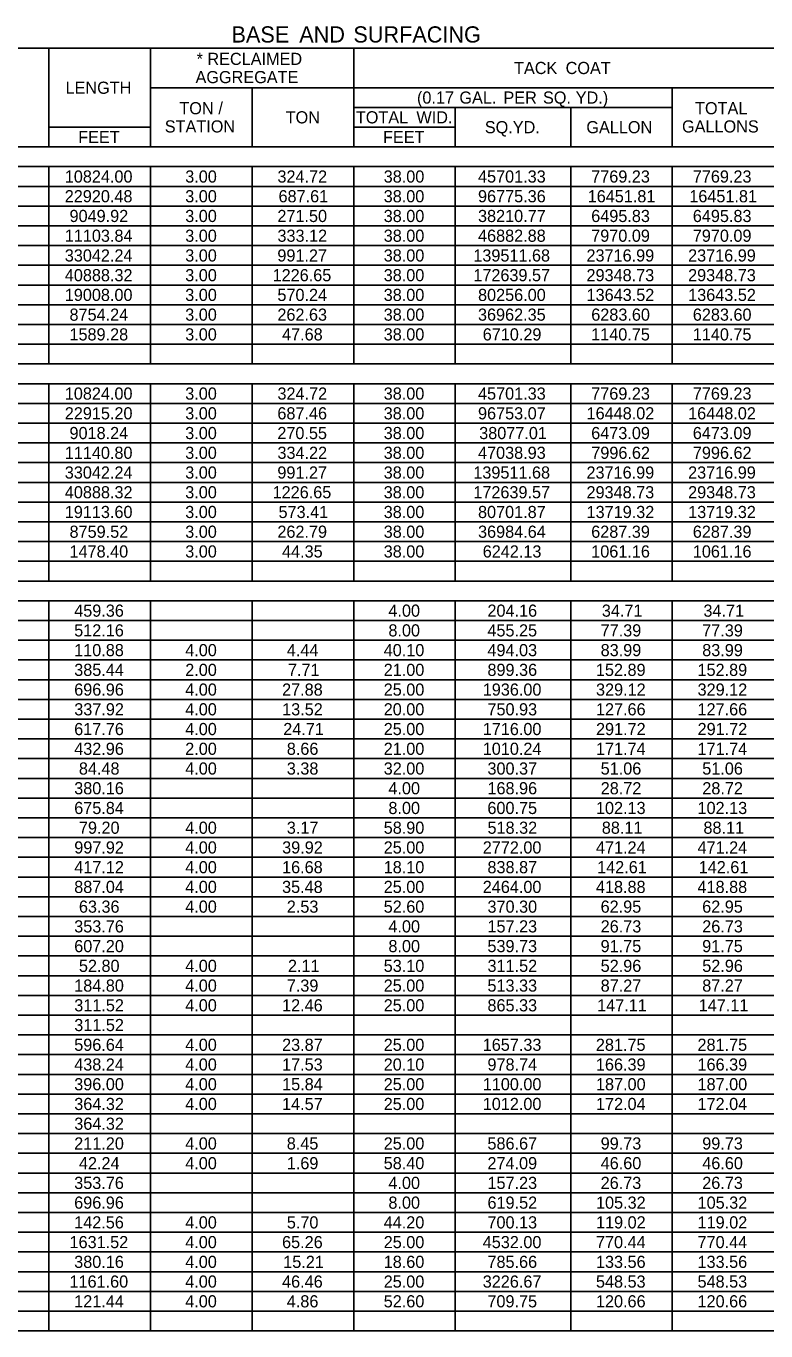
# Model space of a CAD drawing. Extents: x 2261867 to 2275370, y -3124789 to -3122260.
# Drawn here: x 2269779 to 2270145, y -3122908 to -3122263 of the extents above; entities that cross this region are included whole.
import ezdxf

# ---------------------------------------------------------------- set-up
doc = ezdxf.new("R2010")
doc.units = 0
doc.layers.add('Default', color=7, linetype='Continuous')

msp = doc.modelspace()

# ---------------------------------------------------------------- linework, layer by layer
at = {"layer": 'Default'}
for p, q in [((2269380.47, -3122273.85), (2270507.08, -3122273.85)), ((2269790.46, -3122322.6), (2269790.46, -3122273.85)), ((2269840.67, -3122322.6), (2269840.67, -3122273.85)), ((2269941.09, -3122322.6), (2269941.09, -3122273.85)), ((2269840.67, -3122293.35), (2270507.08, -3122293.35)), ((2269890.88, -3122322.6), (2269890.88, -3122293.35)), ((2270098.56, -3122322.6), (2270098.56, -3122293.35)), ((2269941.09, -3122303.1), (2270098.56, -3122303.1)), ((2269991.31, -3122322.6), (2269991.31, -3122303.1)), ((2270048.34, -3122322.6), (2270048.34, -3122303.1)), ((2269790.46, -3122312.85), (2269840.67, -3122312.85)), ((2269840.67, -3122322.6), (2269840.67, -3122312.85)), ((2269941.09, -3122312.85), (2269991.31, -3122312.85)), ((2269991.31, -3122322.6), (2269991.31, -3122312.85)), ((2269380.47, -3122322.6), (2270507.08, -3122322.6)), ((2269840.67, -3122322.6), (2269991.31, -3122322.6)), ((2269991.31, -3122322.6), (2270048.34, -3122322.6)), ((2270048.34, -3122322.6), (2270198.98, -3122322.6)), ((2269380.47, -3122332.35), (2270507.08, -3122332.35)), ((2269790.46, -3122429.85), (2269790.46, -3122332.35)), ((2269790.46, -3122429.85), (2269790.46, -3122332.35)), ((2269840.67, -3122429.85), (2269840.67, -3122332.35)), ((2269840.67, -3122429.85), (2269840.67, -3122332.35)), ((2269890.88, -3122429.85), (2269890.88, -3122332.35)), ((2269890.88, -3122429.85), (2269890.88, -3122332.35)), ((2269941.09, -3122429.85), (2269941.09, -3122332.35)), ((2269941.09, -3122429.85), (2269941.09, -3122332.35)), ((2269991.31, -3122429.85), (2269991.31, -3122332.35)), ((2269991.31, -3122429.85), (2269991.31, -3122332.35)), ((2270048.34, -3122429.85), (2270048.34, -3122332.35)), ((2270048.34, -3122429.85), (2270048.34, -3122332.35)), ((2270098.56, -3122429.85), (2270098.56, -3122332.35)), ((2270098.56, -3122429.85), (2270098.56, -3122332.35)), ((2269380.47, -3122342.1), (2270507.08, -3122342.1)), ((2269380.47, -3122351.85), (2270507.08, -3122351.85)), ((2269380.47, -3122361.6), (2270507.08, -3122361.6)), ((2269380.47, -3122371.35), (2270507.08, -3122371.35)), ((2269380.47, -3122381.1), (2270507.08, -3122381.1)), ((2269380.47, -3122390.85), (2270507.08, -3122390.85)), ((2269380.47, -3122400.6), (2270507.08, -3122400.6)), ((2269380.47, -3122410.35), (2270507.08, -3122410.35)), ((2269380.47, -3122420.1), (2270507.08, -3122420.1)), ((2269380.47, -3122429.85), (2270507.08, -3122429.85)), ((2269380.47, -3122429.85), (2270507.08, -3122429.85)), ((2269380.47, -3122439.6), (2270507.08, -3122439.6)), ((2269790.46, -3122537.1), (2269790.46, -3122439.6)), ((2269790.46, -3122537.1), (2269790.46, -3122439.6)), ((2269840.67, -3122537.1), (2269840.67, -3122439.6)), ((2269840.67, -3122537.1), (2269840.67, -3122439.6)), ((2269890.88, -3122537.1), (2269890.88, -3122439.6)), ((2269890.88, -3122537.1), (2269890.88, -3122439.6)), ((2269941.09, -3122537.1), (2269941.09, -3122439.6)), ((2269941.09, -3122537.1), (2269941.09, -3122439.6)), ((2269991.31, -3122537.1), (2269991.31, -3122439.6)), ((2269991.31, -3122537.1), (2269991.31, -3122439.6)), ((2270048.34, -3122537.1), (2270048.34, -3122439.6)), ((2270048.34, -3122537.1), (2270048.34, -3122439.6)), ((2270098.56, -3122537.1), (2270098.56, -3122439.6)), ((2270098.56, -3122537.1), (2270098.56, -3122439.6)), ((2269380.47, -3122449.35), (2270507.08, -3122449.35)), ((2269380.47, -3122459.1), (2270507.08, -3122459.1)), ((2269380.47, -3122468.85), (2270507.08, -3122468.85)), ((2269380.47, -3122478.6), (2270507.08, -3122478.6)), ((2269380.47, -3122488.35), (2270507.08, -3122488.35)), ((2269380.47, -3122498.1), (2270507.08, -3122498.1)), ((2269380.47, -3122507.85), (2270507.08, -3122507.85)), ((2269380.47, -3122517.6), (2270507.08, -3122517.6)), ((2269380.47, -3122527.35), (2270507.08, -3122527.35)), ((2269380.47, -3122537.1), (2270507.08, -3122537.1)), ((2269380.47, -3122537.1), (2270507.08, -3122537.1)), ((2269380.47, -3122546.85), (2270507.08, -3122546.85)), ((2269790.46, -3122888.1), (2269790.46, -3122546.85)), ((2269790.46, -3122907.6), (2269790.46, -3122546.85)), ((2269840.67, -3122897.85), (2269840.67, -3122546.85)), ((2269840.67, -3122907.6), (2269840.67, -3122546.85)), ((2269890.88, -3122897.85), (2269890.88, -3122546.85)), ((2269890.88, -3122907.6), (2269890.88, -3122546.85)), ((2269941.09, -3122878.35), (2269941.09, -3122546.85)), ((2269941.09, -3122907.6), (2269941.09, -3122546.85)), ((2269991.31, -3122878.35), (2269991.31, -3122546.85)), ((2269991.31, -3122907.6), (2269991.31, -3122546.85)), ((2270048.34, -3122907.6), (2270048.34, -3122546.85)), ((2270048.34, -3122907.6), (2270048.34, -3122546.85)), ((2270098.56, -3122907.6), (2270098.56, -3122546.85)), ((2270098.56, -3122907.6), (2270098.56, -3122546.85)), ((2269380.47, -3122556.6), (2270507.08, -3122556.6)), ((2269380.47, -3122566.35), (2270507.08, -3122566.35)), ((2269380.47, -3122576.1), (2270507.08, -3122576.1)), ((2269380.47, -3122585.85), (2270507.08, -3122585.85)), ((2269380.47, -3122595.6), (2270507.08, -3122595.6)), ((2269380.47, -3122605.35), (2270507.08, -3122605.35)), ((2269380.47, -3122615.1), (2270507.08, -3122615.1)), ((2269380.47, -3122624.85), (2270507.08, -3122624.85)), ((2269380.47, -3122634.6), (2270507.08, -3122634.6)), ((2269380.47, -3122644.35), (2270507.08, -3122644.35)), ((2269380.47, -3122654.1), (2270507.08, -3122654.1)), ((2269380.47, -3122663.85), (2270507.08, -3122663.85)), ((2269380.47, -3122673.6), (2270507.08, -3122673.6)), ((2269380.47, -3122683.35), (2270507.08, -3122683.35)), ((2269380.47, -3122693.1), (2270507.08, -3122693.1)), ((2269380.47, -3122702.85), (2270507.08, -3122702.85)), ((2269380.47, -3122712.6), (2270507.08, -3122712.6)), ((2269380.47, -3122722.35), (2270507.08, -3122722.35)), ((2269380.47, -3122732.1), (2270507.08, -3122732.1)), ((2269380.47, -3122741.85), (2270507.08, -3122741.85)), ((2269380.47, -3122751.6), (2270507.08, -3122751.6)), ((2269380.47, -3122761.35), (2270507.08, -3122761.35)), ((2269380.47, -3122771.1), (2270507.08, -3122771.1)), ((2269380.47, -3122780.85), (2270507.08, -3122780.85)), ((2269380.47, -3122790.6), (2270507.08, -3122790.6)), ((2269380.47, -3122800.35), (2270507.08, -3122800.35)), ((2269380.47, -3122810.1), (2270507.08, -3122810.1)), ((2269380.47, -3122819.85), (2270507.08, -3122819.85)), ((2269380.47, -3122829.6), (2270507.08, -3122829.6)), ((2269380.47, -3122839.35), (2270507.08, -3122839.35)), ((2269380.47, -3122849.1), (2270507.08, -3122849.1)), ((2269380.47, -3122858.85), (2270507.08, -3122858.85)), ((2269380.47, -3122868.6), (2270507.08, -3122868.6)), ((2269380.47, -3122878.35), (2270507.08, -3122878.35)), ((2269380.47, -3122888.1), (2270507.08, -3122888.1)), ((2269380.47, -3122897.85), (2270507.08, -3122897.85)), ((2269790.46, -3122907.6), (2269790.46, -3122897.85)), ((2269840.67, -3122897.85), (2269890.88, -3122897.85)), ((2269890.88, -3122897.85), (2269941.09, -3122897.85)), ((2269941.09, -3122897.85), (2269991.31, -3122897.85)), ((2269991.31, -3122897.85), (2270507.08, -3122897.85)), ((2269380.47, -3122907.6), (2270507.08, -3122907.6)), ((2269480.89, -3122907.6), (2269790.46, -3122907.6)), ((2269790.46, -3122907.6), (2269991.31, -3122907.6)), ((2269991.31, -3122907.6), (2270507.08, -3122907.6))]:
    msp.add_line(p, q, dxfattribs=at)

# ---------------------------------------------------------------- texts
for s, height, p in [('BASE', 8, (2269880.7, -3122271.02)), (' AND', 8, (2269911.21, -3122271.02)), (' SURFACING', 8, (2269937.97, -3122271.02)), ('*', 6, (2269863.47, -3122282.1)), (' RECLAIMED', 6, (2269866.55, -3122282.1)), ('AGGREGATE', 6, (2269862.91, -3122291.1)), ('TACK', 6, (2270020.34, -3122286.6)), (' COAT', 6, (2270043.61, -3122286.6)), ('LENGTH', 6, (2269798.65, -3122296.35)), ('(0.17', 6, (2269972.38, -3122301.22)), (' GAL.', 6, (2269991.11, -3122301.22)), (' PER', 6, (2270012.89, -3122301.22)), (' SQ.', 6, (2270032.42, -3122301.22)), (' YD.)', 6, (2270048.61, -3122301.22)), ('TON', 6, (2269854.93, -3122306.47)), (' /', 6, (2269871.96, -3122306.47)), ('TON', 6, (2269907.47, -3122310.97)), ('TOTAL', 6, (2269942.17, -3122310.97)), (' WID.', 6, (2269969.86, -3122310.97)), ('TOTAL', 6, (2270109.82, -3122306.47)), ('STATION', 6, (2269847.71, -3122315.47)), ('SQ.YD.', 6, (2270005.9, -3122315.85)), ('GALLON', 6, (2270056.09, -3122315.85)), ('GALLONS', 6, (2270103.37, -3122315.47)), ('FEET', 6, (2269804.93, -3122320.72)), ('FEET', 6, (2269955.57, -3122320.72)), ('10824.00', 6, (2269798.29, -3122340.22)), ('3.00', 6, (2269857.82, -3122340.22)), ('324.72', 6, (2269903.4, -3122340.22)), ('38.00', 6, (2269955.92, -3122340.22)), ('45701.33', 6, (2270002.54, -3122340.22)), ('7769.23', 6, (2270058.5, -3122340.22)), ('7769.23', 6, (2270108.71, -3122340.22)), ('22920.48', 6, (2269798.27, -3122349.97)), ('3.00', 6, (2269857.82, -3122349.97)), ('687.61', 6, (2269903.94, -3122349.97)), ('38.00', 6, (2269955.92, -3122349.97)), ('96775.36', 6, (2270002.54, -3122349.97)), ('16451.81', 6, (2270056.75, -3122349.97)), ('16451.81', 6, (2270106.96, -3122349.97)), ('9049.92', 6, (2269800.64, -3122359.72)), ('3.00', 6, (2269857.82, -3122359.72)), ('271.50', 6, (2269903.37, -3122359.72)), ('38.00', 6, (2269955.92, -3122359.72)), ('38210.77', 6, (2270002.54, -3122359.72)), ('6495.83', 6, (2270058.5, -3122359.72)), ('6495.83', 6, (2270108.71, -3122359.72)), ('11103.84', 6, (2269798.29, -3122369.47)), ('3.00', 6, (2269857.82, -3122369.47)), ('333.12', 6, (2269903.4, -3122369.47)), ('38.00', 6, (2269955.92, -3122369.47)), ('46882.88', 6, (2270002.54, -3122369.47)), ('7970.09', 6, (2270058.49, -3122369.47)), ('7970.09', 6, (2270108.7, -3122369.47)), ('33042.24', 6, (2269798.29, -3122379.22)), ('3.00', 6, (2269857.82, -3122379.22)), ('991.27', 6, (2269903.36, -3122379.22)), ('38.00', 6, (2269955.92, -3122379.22)), ('139511.68', 6, (2270000.21, -3122379.22)), ('23716.99', 6, (2270056.16, -3122379.22)), ('23716.99', 6, (2270106.37, -3122379.22)), ('40888.32', 6, (2269798.31, -3122388.97)), ('3.00', 6, (2269857.82, -3122388.97)), ('1226.65', 6, (2269901.01, -3122388.97)), ('38.00', 6, (2269955.92, -3122388.97)), ('172639.57', 6, (2270000.21, -3122388.97)), ('29348.73', 6, (2270056.17, -3122388.97)), ('29348.73', 6, (2270106.38, -3122388.97)), ('19008.00', 6, (2269798.29, -3122398.72)), ('3.00', 6, (2269857.82, -3122398.72)), ('570.24', 6, (2269903.38, -3122398.72)), ('38.00', 6, (2269955.92, -3122398.72)), ('80256.00', 6, (2270002.55, -3122398.72)), ('13643.52', 6, (2270056.2, -3122398.72)), ('13643.52', 6, (2270106.41, -3122398.72)), ('8754.24', 6, (2269800.62, -3122408.47)), ('3.00', 6, (2269857.82, -3122408.47)), ('262.63', 6, (2269903.36, -3122408.47)), ('38.00', 6, (2269955.92, -3122408.47)), ('36962.35', 6, (2270002.52, -3122408.47)), ('6283.60', 6, (2270058.51, -3122408.47)), ('6283.60', 6, (2270108.72, -3122408.47)), ('1589.28', 6, (2269800.6, -3122418.22)), ('3.00', 6, (2269857.82, -3122418.22)), ('47.68', 6, (2269905.69, -3122418.22)), ('38.00', 6, (2269955.92, -3122418.22)), ('6710.29', 6, (2270004.87, -3122418.22)), ('1140.75', 6, (2270058.47, -3122418.22)), ('1140.75', 6, (2270108.69, -3122418.22)), ('10824.00', 6, (2269798.29, -3122447.47)), ('3.00', 6, (2269857.82, -3122447.47)), ('324.72', 6, (2269903.4, -3122447.47)), ('38.00', 6, (2269955.92, -3122447.47)), ('45701.33', 6, (2270002.54, -3122447.47)), ('7769.23', 6, (2270058.5, -3122447.47)), ('7769.23', 6, (2270108.71, -3122447.47)), ('22915.20', 6, (2269798.29, -3122457.22)), ('3.00', 6, (2269857.82, -3122457.22)), ('687.46', 6, (2269903.36, -3122457.22)), ('38.00', 6, (2269955.92, -3122457.22)), ('96753.07', 6, (2270002.54, -3122457.22)), ('16448.02', 6, (2270056.2, -3122457.22)), ('16448.02', 6, (2270106.41, -3122457.22)), ('9018.24', 6, (2269800.62, -3122466.97)), ('3.00', 6, (2269857.82, -3122466.97)), ('270.55', 6, (2269903.34, -3122466.97)), ('38.00', 6, (2269955.92, -3122466.97)), ('38077.01', 6, (2270003.12, -3122466.97)), ('6473.09', 6, (2270058.49, -3122466.97)), ('6473.09', 6, (2270108.7, -3122466.97)), ('11140.80', 6, (2269798.29, -3122476.72)), ('3.00', 6, (2269857.82, -3122476.72)), ('334.22', 6, (2269903.4, -3122476.72)), ('38.00', 6, (2269955.92, -3122476.72)), ('47038.93', 6, (2270002.54, -3122476.72)), ('7996.62', 6, (2270058.53, -3122476.72)), ('7996.62', 6, (2270108.74, -3122476.72)), ('33042.24', 6, (2269798.29, -3122486.47)), ('3.00', 6, (2269857.82, -3122486.47)), ('991.27', 6, (2269903.36, -3122486.47)), ('38.00', 6, (2269955.92, -3122486.47)), ('139511.68', 6, (2270000.21, -3122486.47)), ('23716.99', 6, (2270056.16, -3122486.47)), ('23716.99', 6, (2270106.37, -3122486.47)), ('40888.32', 6, (2269798.31, -3122496.22)), ('3.00', 6, (2269857.82, -3122496.22)), ('1226.65', 6, (2269901.01, -3122496.22)), ('38.00', 6, (2269955.92, -3122496.22)), ('172639.57', 6, (2270000.21, -3122496.22)), ('29348.73', 6, (2270056.17, -3122496.22)), ('29348.73', 6, (2270106.38, -3122496.22)), ('19113.60', 6, (2269798.29, -3122505.97)), ('3.00', 6, (2269857.82, -3122505.97)), ('573.41', 6, (2269903.94, -3122505.97)), ('38.00', 6, (2269955.92, -3122505.97)), ('80701.87', 6, (2270002.54, -3122505.97)), ('13719.32', 6, (2270056.2, -3122505.97)), ('13719.32', 6, (2270106.41, -3122505.97)), ('8759.52', 6, (2269800.64, -3122515.72)), ('3.00', 6, (2269857.82, -3122515.72)), ('262.79', 6, (2269903.36, -3122515.72)), ('38.00', 6, (2269955.92, -3122515.72)), ('36984.64', 6, (2270002.55, -3122515.72)), ('6287.39', 6, (2270058.49, -3122515.72)), ('6287.39', 6, (2270108.7, -3122515.72)), ('1478.40', 6, (2269800.62, -3122525.47)), ('3.00', 6, (2269857.82, -3122525.47)), ('44.35', 6, (2269905.67, -3122525.47)), ('38.00', 6, (2269955.92, -3122525.47)), ('6242.13', 6, (2270004.87, -3122525.47)), ('1061.16', 6, (2270058.5, -3122525.47)), ('1061.16', 6, (2270108.71, -3122525.47)), ('459.36', 6, (2269802.94, -3122554.72)), ('4.00', 6, (2269958.25, -3122554.72)), ('204.16', 6, (2270007.2, -3122554.72)), ('34.71', 6, (2270063.74, -3122554.72)), ('34.71', 6, (2270113.95, -3122554.72)), ('512.16', 6, (2269802.94, -3122564.47)), ('8.00', 6, (2269958.25, -3122564.47)), ('455.25', 6, (2270007.18, -3122564.47)), ('77.39', 6, (2270063.15, -3122564.47)), ('77.39', 6, (2270113.36, -3122564.47)), ('110.88', 6, (2269802.93, -3122574.22)), ('4.00', 6, (2269857.82, -3122574.22)), ('4.44', 6, (2269908.04, -3122574.22)), ('40.10', 6, (2269955.92, -3122574.22)), ('494.03', 6, (2270007.2, -3122574.22)), ('83.99', 6, (2270063.15, -3122574.22)), ('83.99', 6, (2270113.36, -3122574.22)), ('385.44', 6, (2269802.95, -3122583.97)), ('2.00', 6, (2269857.82, -3122583.97)), ('7.71', 6, (2269908.6, -3122583.97)), ('21.00', 6, (2269955.92, -3122583.97)), ('899.36', 6, (2270007.2, -3122583.97)), ('152.89', 6, (2270060.82, -3122583.97)), ('152.89', 6, (2270111.03, -3122583.97)), ('696.96', 6, (2269802.94, -3122593.72)), ('4.00', 6, (2269857.82, -3122593.72)), ('27.88', 6, (2269905.69, -3122593.72)), ('25.00', 6, (2269955.92, -3122593.72)), ('1936.00', 6, (2270004.88, -3122593.72)), ('329.12', 6, (2270060.86, -3122593.72)), ('329.12', 6, (2270111.07, -3122593.72)), ('337.92', 6, (2269802.97, -3122603.47)), ('4.00', 6, (2269857.82, -3122603.47)), ('13.52', 6, (2269905.73, -3122603.47)), ('20.00', 6, (2269955.92, -3122603.47)), ('750.93', 6, (2270007.2, -3122603.47)), ('127.66', 6, (2270060.83, -3122603.47)), ('127.66', 6, (2270111.04, -3122603.47)), ('617.76', 6, (2269802.94, -3122613.22)), ('4.00', 6, (2269857.82, -3122613.22)), ('24.71', 6, (2269906.27, -3122613.22)), ('25.00', 6, (2269955.92, -3122613.22)), ('1716.00', 6, (2270004.88, -3122613.22)), ('291.72', 6, (2270060.86, -3122613.22)), ('291.72', 6, (2270111.07, -3122613.22)), ('432.96', 6, (2269802.94, -3122622.97)), ('2.00', 6, (2269857.82, -3122622.97)), ('8.66', 6, (2269908.02, -3122622.97)), ('21.00', 6, (2269955.92, -3122622.97)), ('1010.24', 6, (2270004.88, -3122622.97)), ('171.74', 6, (2270060.84, -3122622.97)), ('171.74', 6, (2270111.05, -3122622.97)), ('84.48', 6, (2269805.26, -3122632.72)), ('4.00', 6, (2269857.82, -3122632.72)), ('3.38', 6, (2269908.02, -3122632.72)), ('32.00', 6, (2269955.92, -3122632.72)), ('300.37', 6, (2270007.2, -3122632.72)), ('51.06', 6, (2270063.16, -3122632.72)), ('51.06', 6, (2270113.37, -3122632.72)), ('380.16', 6, (2269802.94, -3122642.47)), ('4.00', 6, (2269958.25, -3122642.47)), ('168.96', 6, (2270007.2, -3122642.47)), ('28.72', 6, (2270063.19, -3122642.47)), ('28.72', 6, (2270113.4, -3122642.47)), ('675.84', 6, (2269802.95, -3122652.22)), ('8.00', 6, (2269958.25, -3122652.22)), ('600.75', 6, (2270007.18, -3122652.22)), ('102.13', 6, (2270060.83, -3122652.22)), ('102.13', 6, (2270111.04, -3122652.22)), ('79.20', 6, (2269805.28, -3122661.97)), ('4.00', 6, (2269857.82, -3122661.97)), ('3.17', 6, (2269908.02, -3122661.97)), ('58.90', 6, (2269955.92, -3122661.97)), ('518.32', 6, (2270007.23, -3122661.97)), ('88.11', 6, (2270063.74, -3122661.97)), ('88.11', 6, (2270113.95, -3122661.97)), ('997.92', 6, (2269802.97, -3122671.72)), ('4.00', 6, (2269857.82, -3122671.72)), ('39.92', 6, (2269905.73, -3122671.72)), ('25.00', 6, (2269955.92, -3122671.72)), ('2772.00', 6, (2270004.88, -3122671.72)), ('471.24', 6, (2270060.84, -3122671.72)), ('471.24', 6, (2270111.05, -3122671.72)), ('417.12', 6, (2269802.97, -3122681.47)), ('4.00', 6, (2269857.82, -3122681.47)), ('16.68', 6, (2269905.69, -3122681.47)), ('18.10', 6, (2269955.92, -3122681.47)), ('838.87', 6, (2270007.2, -3122681.47)), ('142.61', 6, (2270061.41, -3122681.47)), ('142.61', 6, (2270111.62, -3122681.47)), ('887.04', 6, (2269802.95, -3122691.22)), ('4.00', 6, (2269857.82, -3122691.22)), ('35.48', 6, (2269905.69, -3122691.22)), ('25.00', 6, (2269955.92, -3122691.22)), ('2464.00', 6, (2270004.88, -3122691.22)), ('418.88', 6, (2270060.82, -3122691.22)), ('418.88', 6, (2270111.03, -3122691.22)), ('63.36', 6, (2269805.27, -3122700.97)), ('4.00', 6, (2269857.82, -3122700.97)), ('2.53', 6, (2269908.02, -3122700.97)), ('52.60', 6, (2269955.92, -3122700.97)), ('370.30', 6, (2270007.21, -3122700.97)), ('62.95', 6, (2270063.13, -3122700.97)), ('62.95', 6, (2270113.35, -3122700.97)), ('353.76', 6, (2269802.94, -3122710.72)), ('4.00', 6, (2269958.25, -3122710.72)), ('157.23', 6, (2270007.2, -3122710.72)), ('26.73', 6, (2270063.16, -3122710.72)), ('26.73', 6, (2270113.37, -3122710.72)), ('607.20', 6, (2269802.95, -3122720.47)), ('8.00', 6, (2269958.25, -3122720.47)), ('539.73', 6, (2270007.2, -3122720.47)), ('91.75', 6, (2270063.13, -3122720.47)), ('91.75', 6, (2270113.35, -3122720.47)), ('52.80', 6, (2269805.28, -3122730.22)), ('4.00', 6, (2269857.82, -3122730.22)), ('2.11', 6, (2269908.6, -3122730.22)), ('53.10', 6, (2269955.92, -3122730.22)), ('311.52', 6, (2270007.23, -3122730.22)), ('52.96', 6, (2270063.16, -3122730.22)), ('52.96', 6, (2270113.37, -3122730.22)), ('184.80', 6, (2269802.95, -3122739.97)), ('4.00', 6, (2269857.82, -3122739.97)), ('7.39', 6, (2269908.02, -3122739.97)), ('25.00', 6, (2269955.92, -3122739.97)), ('513.33', 6, (2270007.2, -3122739.97)), ('87.27', 6, (2270063.16, -3122739.97)), ('87.27', 6, (2270113.37, -3122739.97)), ('311.52', 6, (2269802.97, -3122749.72)), ('4.00', 6, (2269857.82, -3122749.72)), ('12.46', 6, (2269905.69, -3122749.72)), ('25.00', 6, (2269955.92, -3122749.72)), ('865.33', 6, (2270007.2, -3122749.72)), ('147.11', 6, (2270061.41, -3122749.72)), ('147.11', 6, (2270111.62, -3122749.72)), ('311.52', 6, (2269802.97, -3122759.47)), ('596.64', 6, (2269802.95, -3122769.22)), ('4.00', 6, (2269857.82, -3122769.22)), ('23.87', 6, (2269905.69, -3122769.22)), ('25.00', 6, (2269955.92, -3122769.22)), ('1657.33', 6, (2270004.87, -3122769.22)), ('281.75', 6, (2270060.8, -3122769.22)), ('281.75', 6, (2270111.02, -3122769.22)), ('438.24', 6, (2269802.95, -3122778.97)), ('4.00', 6, (2269857.82, -3122778.97)), ('17.53', 6, (2269905.69, -3122778.97)), ('20.10', 6, (2269955.92, -3122778.97)), ('978.74', 6, (2270007.21, -3122778.97)), ('166.39', 6, (2270060.82, -3122778.97)), ('166.39', 6, (2270111.03, -3122778.97)), ('396.00', 6, (2269802.95, -3122788.72)), ('4.00', 6, (2269857.82, -3122788.72)), ('15.84', 6, (2269905.71, -3122788.72)), ('25.00', 6, (2269955.92, -3122788.72)), ('1100.00', 6, (2270004.88, -3122788.72)), ('187.00', 6, (2270060.84, -3122788.72)), ('187.00', 6, (2270111.05, -3122788.72)), ('364.32', 6, (2269802.97, -3122798.47)), ('4.00', 6, (2269857.82, -3122798.47)), ('14.57', 6, (2269905.69, -3122798.47)), ('25.00', 6, (2269955.92, -3122798.47)), ('1012.00', 6, (2270004.88, -3122798.47)), ('172.04', 6, (2270060.84, -3122798.47)), ('172.04', 6, (2270111.05, -3122798.47)), ('364.32', 6, (2269802.97, -3122808.22)), ('211.20', 6, (2269802.95, -3122817.97)), ('4.00', 6, (2269857.82, -3122817.97)), ('8.45', 6, (2269908, -3122817.97)), ('25.00', 6, (2269955.92, -3122817.97)), ('586.67', 6, (2270007.2, -3122817.97)), ('99.73', 6, (2270063.16, -3122817.97)), ('99.73', 6, (2270113.37, -3122817.97)), ('42.24', 6, (2269805.28, -3122827.72)), ('4.00', 6, (2269857.82, -3122827.72)), ('1.69', 6, (2269908.02, -3122827.72)), ('58.40', 6, (2269955.92, -3122827.72)), ('274.09', 6, (2270007.2, -3122827.72)), ('46.60', 6, (2270063.17, -3122827.72)), ('46.60', 6, (2270113.38, -3122827.72)), ('353.76', 6, (2269802.94, -3122837.47)), ('4.00', 6, (2269958.25, -3122837.47)), ('157.23', 6, (2270007.2, -3122837.47)), ('26.73', 6, (2270063.16, -3122837.47)), ('26.73', 6, (2270113.37, -3122837.47)), ('696.96', 6, (2269802.94, -3122847.22)), ('8.00', 6, (2269958.25, -3122847.22)), ('619.52', 6, (2270007.23, -3122847.22)), ('105.32', 6, (2270060.86, -3122847.22)), ('105.32', 6, (2270111.07, -3122847.22)), ('142.56', 6, (2269802.94, -3122856.97)), ('4.00', 6, (2269857.82, -3122856.97)), ('5.70', 6, (2269908.04, -3122856.97)), ('44.20', 6, (2269955.92, -3122856.97)), ('700.13', 6, (2270007.2, -3122856.97)), ('119.02', 6, (2270060.86, -3122856.97)), ('119.02', 6, (2270111.07, -3122856.97)), ('1631.52', 6, (2269800.64, -3122866.72)), ('4.00', 6, (2269857.82, -3122866.72)), ('65.26', 6, (2269905.69, -3122866.72)), ('25.00', 6, (2269955.92, -3122866.72)), ('4532.00', 6, (2270004.88, -3122866.72)), ('770.44', 6, (2270060.84, -3122866.72)), ('770.44', 6, (2270111.05, -3122866.72)), ('380.16', 6, (2269802.94, -3122876.47)), ('4.00', 6, (2269857.82, -3122876.47)), ('15.21', 6, (2269906.27, -3122876.47)), ('18.60', 6, (2269955.92, -3122876.47)), ('785.66', 6, (2270007.2, -3122876.47)), ('133.56', 6, (2270060.83, -3122876.47)), ('133.56', 6, (2270111.04, -3122876.47)), ('1161.60', 6, (2269800.62, -3122886.22)), ('4.00', 6, (2269857.82, -3122886.22)), ('46.46', 6, (2269905.69, -3122886.22)), ('25.00', 6, (2269955.92, -3122886.22)), ('3226.67', 6, (2270004.87, -3122886.22)), ('548.53', 6, (2270060.83, -3122886.22)), ('548.53', 6, (2270111.04, -3122886.22)), ('121.44', 6, (2269802.95, -3122895.97)), ('4.00', 6, (2269857.82, -3122895.97)), ('4.86', 6, (2269908.02, -3122895.97)), ('52.60', 6, (2269955.92, -3122895.97)), ('709.75', 6, (2270007.18, -3122895.97)), ('120.66', 6, (2270060.83, -3122895.97)), ('120.66', 6, (2270111.04, -3122895.97))]:
    msp.add_text(s, height=height, dxfattribs=at).set_placement(p)

doc.saveas('drawing.dxf')
